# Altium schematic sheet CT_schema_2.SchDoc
size 300 x 163 mm
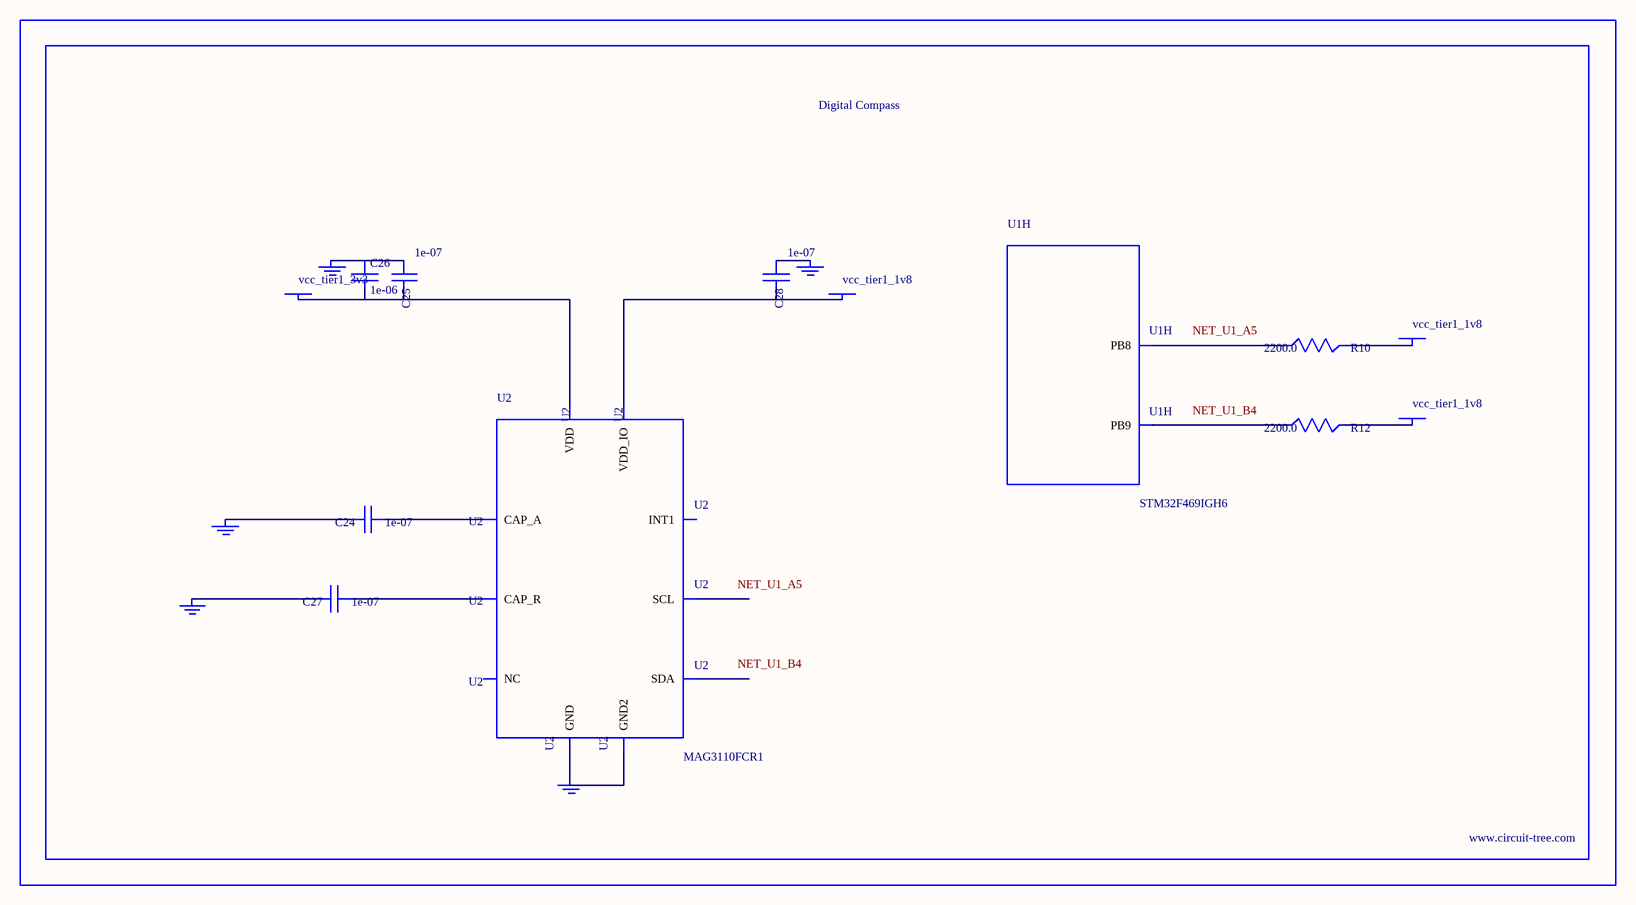
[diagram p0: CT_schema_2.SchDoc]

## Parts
BORDER1  (no value)
C24  1e-07  [C0402]
C25  1e-07  [C0402]
C26  1e-06  [C0603]
C27  1e-07  [C0402]
C28  1e-07  [C0402]
GND_INSTANCE_1_0  (no value)
GND_INSTANCE_1_1  (no value)
GND_INSTANCE_1_2  (no value)
GND_INSTANCE_1_3  (no value)
GND_INSTANCE_1_4  (no value)
POWER_INSTANCE_1_0  vcc_tier1_3v3
POWER_INSTANCE_1_1  vcc_tier1_1v8
POWER_INSTANCE_1_2  vcc_tier1_1v8
POWER_INSTANCE_1_3  vcc_tier1_1v8
R10  2200.0  [R0603]
R12  2200.0  [R0603]
U1  STM32F469IGH6  [UFBGA176]  (part H of 16)
U2  MAG3110FCR1  [DFN-10]

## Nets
NetC24_1: C24.1 U2.1(CAP_A)
NetC24_2: C24.2 GND_INSTANCE_1_0.0(GND)
NetC25_1: C25.1 C26.1 GND_INSTANCE_1_1.0(GND)
NetC25_2: C25.2 C26.2 POWER_INSTANCE_1_0.0(PWR) U2.2(VDD)
NetC27_1: C27.1 U2.4(CAP_R)
NetC27_2: C27.2 GND_INSTANCE_1_2.0(GND)
NetC28_1: C28.1 GND_INSTANCE_1_3.0(GND)
NetC28_2: C28.2 POWER_INSTANCE_1_1.0(PWR) U2.8(VDD_IO)
NetGND_INSTANCE_1_4_0: GND_INSTANCE_1_4.0(GND) U2.5(GND) U2.10(GND2)
NetPOWER_INSTANCE_1_2_0: POWER_INSTANCE_1_2.0(PWR) R10.2
NetPOWER_INSTANCE_1_3_0: POWER_INSTANCE_1_3.0(PWR) R12.2
NetR10_1: R10.1 U1.A5(PB8)
NetR12_1: R12.1 U1.B4(PB9)

Not connected (* = marked no-connect by the designer): U2 3(NC) 6(SDA) 7(SCL) 9(INT1)

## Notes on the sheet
- Labels drawn without touching a wire or pin: NET_U1_A5, NET_U1_B4

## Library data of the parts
BORDER1 = BORDER_PAGE1
C24 C25 C27 C28 = C0402C104K3RACTU
C26 = C0603C105K3RACTU
GND_INSTANCE_1_0-GND_INSTANCE_1_4 = GND
POWER_INSTANCE_1_0-POWER_INSTANCE_1_3 = PWR
R10 R12 = RC0603JR-072K2L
